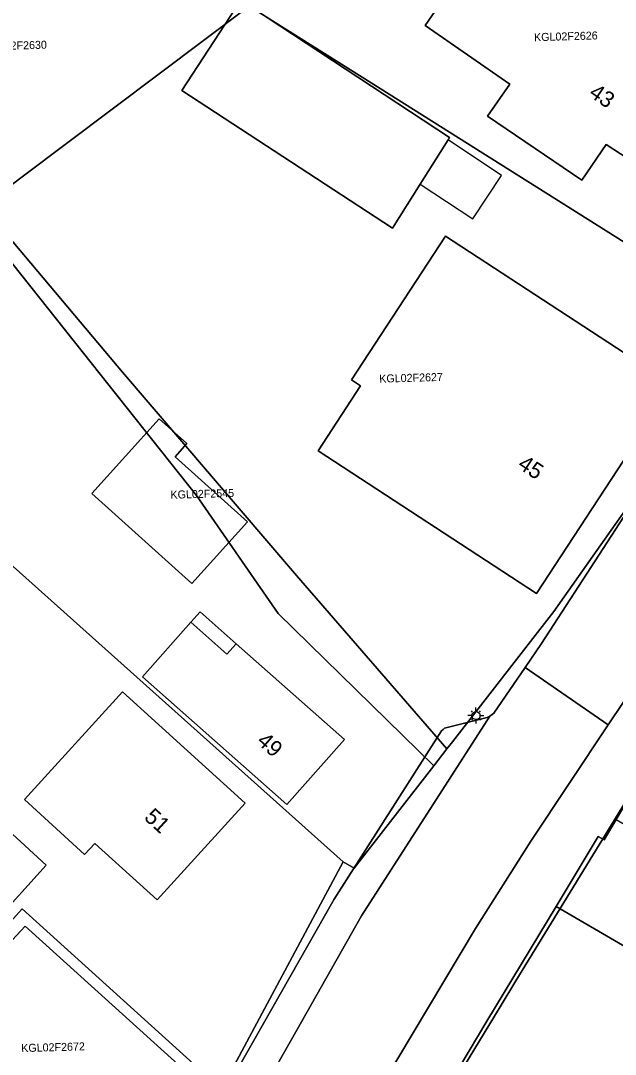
# Model space of a CAD drawing. Extents: x 124901 to 125496, y 515369 to 515789.
# Drawn here: x 125060.1 to 125097.3, y 515624.4 to 515689 of the extents above; entities that cross this region are included whole.
import ezdxf

# ---------------------------------------------------------------- set-up
doc = ezdxf.new("R2010")
doc.units = 0
for name, color, linetype in [('Gebouw', 7, 'Continuous'), ('Lichtmast', 7, 'Continuous'), ('Luifel', 7, 'Continuous'), ('Onbegroeid terrein', 7, 'Continuous'), ('Overige bouwwerk', 7, 'Continuous'), ('Parkeren', 7, 'Continuous'), ('Perceelnummers', 7, 'Continuous'), ('Perceelsgrenzen', 7, 'Continuous'), ('Teksten', 7, 'Continuous'), ('Voetpad', 7, 'Continuous'), ('Wegen drempel verkeerseiland', 7, 'Continuous'), ('Wegen lokale weg', 7, 'Continuous')]:
    doc.layers.add(name, color=color, linetype=linetype)

msp = doc.modelspace()

# ---------------------------------------------------------------- linework, layer by layer
at = {"layer": 'Gebouw'}
for points in [[(125096.737, 515681.215), (125098.51, 515680.037), (125102.984, 515686.589), (125095.901, 515691.504), (125099.16, 515696.274), (125090.537, 515702.263), (125086.904, 515697.005), (125089.809, 515695.053), (125085.411, 515688.655), (125090.712, 515684.992), (125089.312, 515682.989), (125095.208, 515678.973)], [(125073.897, 515690.258), (125070.206, 515684.582), (125083.365, 515675.994), (125085.105, 515678.743), (125086.85, 515681.5), (125086.943, 515681.647)], [(125092.378, 515653.149), (125100.905, 515666.187), (125086.687, 515675.486), (125080.814, 515666.506), (125081.38, 515666.136), (125078.726, 515662.078)], [(125064.579, 515659.397), (125070.831, 515653.774), (125074.302, 515657.633), (125069.777, 515661.703), (125070.514, 515662.523), (125068.787, 515664.076)], [(125070.767, 515651.355), (125067.746, 515647.94), (125076.769, 515639.959), (125080.365, 515644.024), (125073.59, 515650.017), (125073.015, 515649.367)], [(125064.764, 515637.523), (125068.663, 515634.014), (125074.16, 515640.043), (125066.502, 515647.017), (125060.372, 515640.289), (125064.11, 515636.837)], [(125040.85, 515634.817), (125041.741, 515634.005), (125043.969, 515631.974), (125050.63, 515625.902), (125054.984, 515630.678), (125057.086, 515632.984), (125058.033, 515632.121), (125058.465, 515632.595), (125061.732, 515636.179), (125057.219, 515640.293), (125051.004, 515645.957)], [(125058.033, 515632.121), (125057.086, 515632.984), (125054.984, 515630.678), (125050.63, 515625.902), (125051.713, 515624.895), (125052.837, 515626.56), (125058.582, 515622.681), (125058.681, 515622.614), (125059.078, 515623.201), (125065.039, 515619.326), (125064.966, 515619.218), (125066.376, 515618.266), (125069.982, 515623.717), (125060.408, 515632.366), (125059.619, 515631.522), (125058.465, 515632.595)]]:
    msp.add_lwpolyline(points, close=True, dxfattribs=at)
at = {"layer": 'Lichtmast'}
for p, q in [((125088.59, 515645.83), (125088.59, 515646.03)), ((125088.29, 515645.531), (125088.09, 515645.53)), ((125088.378, 515645.318), (125088.306, 515645.247)), ((125088.378, 515645.742), (125088.308, 515645.813)), ((125088.802, 515645.742), (125088.873, 515645.814)), ((125088.802, 515645.318), (125088.872, 515645.247)), ((125088.89, 515645.53), (125089.09, 515645.53)), ((125088.59, 515645.23), (125088.59, 515645.03))]:
    msp.add_line(p, q, dxfattribs=at)
msp.add_circle((125088.59, 515645.53), 0.25, dxfattribs=at)
at = {"layer": 'Luifel'}
msp.add_lwpolyline([(125070.767, 515651.355), (125073.015, 515649.367), (125073.59, 515650.017), (125071.342, 515652.005)], close=True, dxfattribs=at)
at = {"layer": 'Onbegroeid terrein'}
for points in [[(125098.51, 515680.037), (125096.737, 515681.215), (125095.208, 515678.973), (125089.312, 515682.989), (125090.712, 515684.992), (125085.411, 515688.655), (125089.809, 515695.053), (125086.904, 515697.005), (125090.537, 515702.263), (125099.16, 515696.274), (125095.901, 515691.504), (125102.984, 515686.589)], [(125070.206, 515684.582), (125073.897, 515690.258), (125086.943, 515681.647), (125086.85, 515681.5), (125085.105, 515678.743), (125083.365, 515675.994)], [(125100.905, 515666.187), (125092.378, 515653.149), (125078.726, 515662.078), (125081.38, 515666.136), (125080.814, 515666.506), (125086.687, 515675.486)], [(125070.831, 515653.774), (125064.579, 515659.397), (125068.787, 515664.076), (125070.514, 515662.523), (125069.777, 515661.703), (125074.302, 515657.633)], [(125067.746, 515647.94), (125070.767, 515651.355), (125073.015, 515649.367), (125073.59, 515650.017), (125080.365, 515644.024), (125076.769, 515639.959)], [(125068.663, 515634.014), (125064.764, 515637.523), (125064.11, 515636.837), (125060.372, 515640.289), (125066.502, 515647.017), (125074.16, 515640.043)]]:
    msp.add_lwpolyline(points, close=True, dxfattribs=at)
for points in [[(125073.228, 515622.617), (125075.311, 515626.278), (125079.729, 515634.043), (125086.43, 515644.565), (125086.531, 515644.661), (125086.621, 515644.747), (125089.281, 515645.41), (125089.462, 515645.498), (125089.591, 515645.587), (125089.696, 515645.675), (125091.656, 515648.529), (125092.693, 515650.039), (125098.859, 515659.525), (125104.868, 515669.219), (125109.5, 515677.38), (125110.211, 515678.634), (125114.857, 515687.989), (125119.179, 515696.811)], [(125048.014, 515620.914), (125040.883, 515627.512), (125040.275, 515628.074), (125040.949, 515628.785), (125038.849, 515630.72), (125038.783, 515630.605), (125037.856, 515631.465), (125037.954, 515631.568), (125040.589, 515634.339), (125041.383, 515633.628), (125041.741, 515634.005), (125040.85, 515634.817), (125036.851, 515638.565), (125035.174, 515640.137), (125034.992, 515640.308), (125043.035, 515649.188), (125045.067, 515651.432), (125051.004, 515645.957), (125057.219, 515640.293), (125061.732, 515636.179), (125058.465, 515632.595), (125059.619, 515631.522), (125060.408, 515632.366), (125069.982, 515623.717)], [(125149.357, 515623.506), (125153.011, 515630.042), (125151.072, 515631.046), (125151.126, 515631.154), (125144.881, 515634.349), (125137.288, 515638.226), (125135.859, 515638.966), (125123.279, 515644.801), (125122.838, 515644.99), (125120.016, 515646.2), (125117.521, 515647.27), (125111.164, 515649.996), (125110.071, 515650.329), (125108.495, 515650.388), (125107.048, 515650.295), (125105.667, 515649.993), (125104.17, 515649.357), (125103.319, 515648.9), (125091.073, 515628.943), (125090.11, 515627.331), (125083.94, 515617.184)]]:
    msp.add_lwpolyline(points, dxfattribs=at)
at = {"layer": 'Overige bouwwerk'}
msp.add_lwpolyline([(125088.383, 515676.561), (125090.191, 515679.277), (125086.85, 515681.5), (125085.105, 515678.743)], close=True, dxfattribs=at)
at = {"layer": 'Parkeren'}
msp.add_lwpolyline([(125070.056, 515612.85), (125074.966, 515621.628), (125077.049, 515625.289), (125081.443, 515633.011), (125089.462, 515645.498), (125089.281, 515645.41), (125086.621, 515644.747), (125086.531, 515644.661), (125086.43, 515644.565), (125079.729, 515634.043), (125075.311, 515626.278), (125073.228, 515622.617), (125072.2, 515620.809), (125069.519, 515616.097), (125069.537, 515615.75), (125069.565, 515615.51), (125070.086, 515613.465), (125070.15, 515613.216), (125070.135, 515613.049)], close=True, dxfattribs=at)
at = {"layer": 'Perceelsgrenzen'}
for points in [[(125081.473, 515685.414), (125074.421, 515689.851), (125062.069, 515697.48), (125063.132, 515697.834), (125063.426, 515697.932), (125086.431, 515705.598), (125108.544, 515690.373), (125112.041, 515687.866), (125113.735, 515686.647), (125112.864, 515684.95), (125105.41, 515670.408), (125105.386, 515670.369)], [(125057.754, 515677.336), (125045.196, 515692.195), (125056.042, 515695.613), (125062.069, 515697.48), (125074.421, 515689.851), (125060.223, 515679.19)], [(125040.931, 515627.093), (125037.137, 515630.723), (125036.712, 515631.413), (125031.866, 515639.28), (125034.423, 515641.126), (125026.885, 515653.376), (125023.812, 515658.371), (125019.579, 515665.251), (125016.351, 515670.496), (125013.58, 515690.889), (125023.847, 515691.023), (125024.009, 515686.713), (125031.069, 515680.399), (125080.294, 515636.377), (125072.681, 515622.173), (125060.212, 515633.452), (125055.522, 515628.217), (125053.571, 515626.038), (125048.992, 515620.927), (125048.229, 515620.075), (125048.15, 515620.185), (125046.127, 515622.121)], [(125087.116, 515643.882), (125086.956, 515643.676), (125086.773, 515643.441), (125077.371, 515654.277), (125066.493, 515666.995), (125057.754, 515677.336), (125060.223, 515679.19), (125074.421, 515689.851), (125081.473, 515685.414), (125105.386, 515670.369), (125099.087, 515659.997), (125093.45, 515652.027)], [(125080.294, 515636.377), (125031.069, 515680.399), (125036.757, 515681.258), (125051.703, 515682.914), (125057.045, 515676.804), (125058.493, 515675.149), (125071.111, 515659.273), (125076.232, 515651.908), (125085.951, 515642.383), (125080.977, 515635.987)], [(125057.045, 515676.804), (125057.754, 515677.336), (125066.493, 515666.995), (125077.371, 515654.277), (125086.773, 515643.441), (125085.951, 515642.383), (125076.232, 515651.908), (125071.111, 515659.273), (125058.493, 515675.149)], [(125094.787, 515635.584), (125096.223, 515637.971), (125096.611, 515637.757), (125097.361, 515639.025), (125119.387, 515626.196), (125116.825, 515621.224), (125111.621, 515624.256), (125110.434, 515623.79), (125093.595, 515633.603)], [(125072.681, 515622.173), (125069.998, 515617.166), (125069.468, 515616.178), (125064.966, 515619.218), (125065.039, 515619.326), (125059.078, 515623.201), (125058.681, 515622.614), (125058.582, 515622.681), (125053.571, 515626.038), (125055.522, 515628.217), (125060.212, 515633.452)]]:
    msp.add_lwpolyline(points, close=True, dxfattribs=at)
for points in [[(125072.681, 515622.173), (125080.294, 515636.377), (125080.977, 515635.987), (125085.951, 515642.383), (125086.773, 515643.441), (125086.956, 515643.676), (125087.116, 515643.882), (125093.45, 515652.027), (125099.087, 515659.997), (125105.386, 515670.369), (125105.41, 515670.408), (125112.864, 515684.95), (125113.735, 515686.647), (125116.999, 515693.015)], [(125126.585, 515691.761), (125122.019, 515683), (125120.79, 515679.928), (125119.66, 515677.103), (125117.383, 515671.815), (125117.233, 515671.492), (125114.695, 515666.031), (125114.189, 515664.798), (125113.279, 515662.773), (125103.503, 515648.705), (125100.606, 515644.506), (125097.361, 515639.025), (125096.611, 515637.757), (125096.223, 515637.971), (125094.787, 515635.584), (125093.595, 515633.603), (125089.274, 515626.42), (125084.2, 515617.939)], [(125084.2, 515617.939), (125089.274, 515626.42), (125093.595, 515633.603), (125110.434, 515623.79)]]:
    msp.add_lwpolyline(points, dxfattribs=at)
at = {"layer": 'Voetpad'}
for points in [[(125083.94, 515617.184), (125090.11, 515627.331), (125091.073, 515628.943), (125103.319, 515648.9)], [(125098.676, 515647.685), (125096.857, 515644.957), (125092.011, 515637.687), (125088.561, 515632.219), (125078.852, 515615.982)]]:
    msp.add_lwpolyline(points, dxfattribs=at)
at = {"layer": 'Wegen drempel verkeerseiland'}
msp.add_lwpolyline([(125098.859, 515659.525), (125092.693, 515650.039), (125091.656, 515648.529), (125096.857, 515644.957), (125098.676, 515647.685)], dxfattribs=at)
at = {"layer": 'Wegen lokale weg'}
msp.add_lwpolyline([(125063.124, 515587.005), (125070.405, 515600.661), (125078.852, 515615.982), (125088.561, 515632.219), (125092.011, 515637.687), (125096.857, 515644.957), (125091.656, 515648.529), (125089.696, 515645.675), (125089.591, 515645.587), (125089.462, 515645.498), (125081.443, 515633.011), (125077.049, 515625.289), (125074.966, 515621.628), (125070.056, 515612.85), (125065.259, 515604.145), (125064.885, 515603.466), (125062.379, 515598.744), (125058.023, 515590.533), (125057.609, 515589.753), (125063.031, 515586.827)], close=True, dxfattribs=at)

# ---------------------------------------------------------------- texts
at = {"layer": 'Perceelnummers'}
for s, rotation, p in [('KGL02F2626', 1.63094, (125092.225, 515687.665)), ('KGL02F2630', 1.63053, (125057.796, 515687.089)), ('KGL02F2627', 1.63082, (125082.55, 515666.327)), ('KGL02F2545', 1.63067, (125069.5, 515659.075)), ('KGL02F2672', 1.63056, (125060.17, 515624.496))]:
    msp.add_text(s, height=0.5, rotation=rotation, dxfattribs=at).set_placement(p)
at = {"layer": 'Teksten'}
for s, rotation, p in [('43', 325.7, (125095.586, 515684.267)), ('45', 326.8, (125091.135, 515661.038)), ('49', 318.5, (125074.83, 515643.838)), ('51', 317.6, (125067.789, 515639.088))]:
    msp.add_text(s, height=1, rotation=rotation, dxfattribs=at).set_placement(p)

doc.saveas('drawing.dxf')
